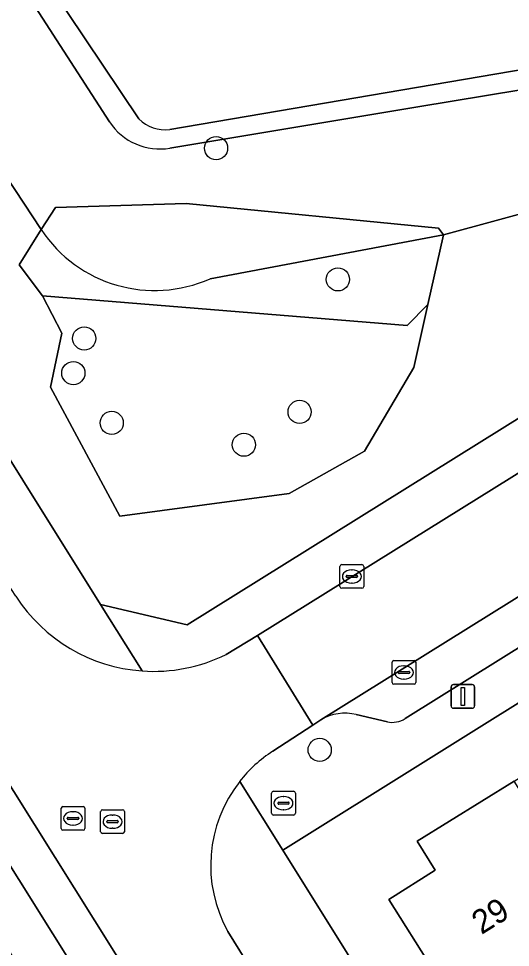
# Model space of a CAD drawing. Extents: x 159664 to 160323, y 385312 to 386115.
# Drawn here: x 159837.52 to 159858.24, y 385888.33 to 385927.51 of the extents above; entities that cross this region are included whole.
import ezdxf

# ---------------------------------------------------------------- set-up
doc = ezdxf.new("R2010")
doc.units = 0
for name, color, linetype in [('IMGEO_Boom', 7, 'Continuous'), ('IMGEO_Brandkraan', 7, 'Continuous'), ('IMGEO_Erf', 7, 'Continuous'), ('IMGEO_Groenvoorziening', 7, 'Continuous'), ('IMGEO_Kolk', 7, 'Continuous'), ('IMGEO_Lichtmast', 7, 'Continuous'), ('IMGEO_Meer_plas_ven_vijver', 7, 'Continuous'), ('IMGEO_Oever', 7, 'Continuous'), ('IMGEO_Pand', 7, 'Continuous'), ('IMGEO_Pand_nummerreeks', 7, 'Continuous'), ('IMGEO_Parkeervlak_open', 7, 'Continuous'), ('IMGEO_Rijbaan_lokaal_open', 7, 'Continuous'), ('IMGEO_Rioolput', 7, 'Continuous'), ('IMGEO_Voetpad_open', 7, 'Continuous')]:
    doc.layers.add(name, color=color, linetype=linetype)

msp = doc.modelspace()

# ---------------------------------------------------------------- linework, layer by layer
at = {"layer": 'IMGEO_Boom'}
for centre in [(159845.842, 385922.048), (159850.977, 385916.513), (159840.289, 385914.022), (159839.829, 385912.56), (159849.363, 385910.923), (159841.446, 385910.459), (159847.015, 385909.539), (159850.209, 385896.665)]:
    msp.add_circle(centre, 0.489, dxfattribs=at)
at = {"layer": 'IMGEO_Brandkraan'}
for p, q in [((159848.182, 385893.993), (159848.182, 385894.845)), ((159848.257, 385894.919), (159849.109, 385894.919)), ((159848.67, 385894.699), (159848.695, 385894.699)), ((159849.183, 385894.845), (159849.183, 385893.993)), ((159848.441, 385894.413), (159848.441, 385894.425)), ((159848.879, 385894.376), (159848.481, 385894.376)), ((159848.484, 385894.462), (159848.882, 385894.462)), ((159848.925, 385894.425), (159848.925, 385894.413)), ((159849.109, 385893.919), (159848.257, 385893.919)), ((159848.693, 385894.139), (159848.668, 385894.139))]:
    msp.add_line(p, q, dxfattribs=at)
for points in [[(159848.182, 385893.993), (159848.182, 385894.845)], [(159848.257, 385894.919), (159849.109, 385894.919)], [(159849.183, 385894.845), (159849.183, 385893.993)], [(159849.109, 385893.919), (159848.257, 385893.919)]]:
    msp.add_lwpolyline(points, dxfattribs=at)
for centre, radius, start, end in [((159848.259, 385894.843), 0.0765, 91.552, 178.448), ((159848.259, 385894.843), 0.0765, 91.552, 178.448), ((159849.107, 385894.843), 0.0765, 1.552, 88.448), ((159849.107, 385894.843), 0.0765, 1.552, 88.448), ((159848.481, 385894.422), 0.0403, 85.8775, 175.7526), ((159848.478, 385894.412), 0.0366, 178.938, 274.7102), ((159848.882, 385894.419), 0.043, 264.8664, 352.4533), ((159848.886, 385894.424), 0.0386, 1.7309, 96.639), ((159848.259, 385893.995), 0.0765, 181.552, 268.448), ((159848.259, 385893.995), 0.0765, 181.552, 268.448), ((159849.107, 385893.995), 0.0765, 271.552, 358.448), ((159849.107, 385893.995), 0.0765, 271.552, 358.448)]:
    msp.add_arc(centre, radius, start, end, dxfattribs=at)
for centre, major_axis, ratio, start_param, end_param in [((159848.669, 385894.419), (-0.387, 0.002), 0.722429, 4.712389, 7.853982), ((159848.694, 385894.419), (-0.39, 0.002), 0.717154, 1.570796, 4.712389)]:
    msp.add_ellipse(centre, major_axis=major_axis, ratio=ratio, start_param=start_param, end_param=end_param, dxfattribs=at)
at = {"layer": 'IMGEO_Erf'}
for points in [[(159910.117, 385903.4), (159897.762, 385923.148), (159848.649, 385892.435), (159862.284, 385870.598)], [(159858.647, 385881.576), (159853.117, 385890.352), (159855.08, 385891.589), (159854.319, 385892.812), (159858.396, 385895.35), (159861.083, 385897.023), (159862.264, 385896.739), (159864.086, 385897.883), (159866.508, 385899.404), (159866.729, 385900.359), (159868.222, 385901.297), (159869.161, 385901.055), (159869.407, 385901.202), (159869.672, 385901.361), (159869.899, 385902.316), (159871.378, 385903.268), (159872.318, 385903.03), (159874.694, 385904.513), (159877.06, 385905.991), (159877.276, 385906.941), (159878.764, 385907.881), (159879.712, 385907.648), (159880.006, 385907.827)]]:
    msp.add_lwpolyline(points, dxfattribs=at)
at = {"layer": 'IMGEO_Groenvoorziening'}
for points in [[(159816.297, 385948.623), (159815.724, 385950.966), (159815.963, 385953.118), (159815.58, 385954.17), (159814.146, 385955.461), (159811.994, 385956.513), (159811.037, 385957.804), (159811.468, 385959.287), (159812.472, 385960.291), (159812.807, 385961.678), (159812.663, 385963.686), (159812.339, 385964.66), (159805.18, 385960.168), (159840.98, 385902.792), (159844.627, 385901.937), (159897.826, 385935.149), (159897.089, 385936.287), (159896.974, 385936.212), (159896.463, 385937.027)], [(159825.341, 385947.546), (159823.184, 385946.559), (159821.022, 385946.602), (159820.348, 385946.616), (159820.789, 385945.508), (159838.479, 385918.611), (159839.072, 385919.548), (159844.581, 385919.713), (159855.219, 385918.667), (159855.427, 385918.399), (159863.832, 385920.689), (159866.297, 385921.953), (159870.044, 385923.874), (159871.106, 385924.495), (159870.716, 385924.674), (159869.124, 385925.404), (159865.913, 385927.638), (159862.758, 385925.65), (159861.486, 385925.086), (159860.136, 385924.752), (159854.341, 385923.788), (159843.899, 385922.051)], [(159841.353, 385923.154), (159833.178, 385935.808), (159832.783, 385936.389), (159832.404, 385936.945), (159825.341, 385947.546)], [(159893.074, 385936.712), (159888.397, 385934.574), (159883.316, 385931.913), (159878.038, 385928.61), (159876.477, 385927.633), (159871.106, 385924.495), (159870.044, 385923.874), (159866.297, 385921.953), (159863.832, 385920.689), (159855.427, 385918.399), (159854.769, 385915.45), (159854.175, 385912.792), (159852.092, 385909.266), (159848.925, 385907.476), (159841.782, 385906.522), (159838.868, 385911.97), (159839.343, 385914.245), (159838.525, 385915.822), (159837.543, 385917.132), (159838.479, 385918.611), (159820.789, 385945.508)], [(159845.593, 385916.542), (159855.427, 385918.399), (159855.219, 385918.667), (159844.581, 385919.713), (159839.072, 385919.548), (159838.479, 385918.611)], [(159838.479, 385918.611), (159837.543, 385917.132), (159838.525, 385915.822), (159853.893, 385914.567), (159854.769, 385915.45), (159855.427, 385918.399), (159845.593, 385916.542)]]:
    msp.add_lwpolyline(points, dxfattribs=at)
msp.add_lwpolyline([(159854.175, 385912.792), (159854.769, 385915.45), (159853.893, 385914.567), (159838.525, 385915.822), (159839.343, 385914.245), (159838.868, 385911.97), (159841.782, 385906.522), (159848.925, 385907.476), (159852.092, 385909.266)], close=True, dxfattribs=at)
for centre, radius, start, end in [((159843.474, 385924.559), 2.544, 213.5278, 279.6249), ((159843.255, 385921.769), 5.726, 213.4728, 294.0947), ((159843.255, 385921.769), 5.726, 213.4728, 294.0947)]:
    msp.add_arc(centre, radius, start, end, dxfattribs=at)
at = {"layer": 'IMGEO_Kolk'}
for p, q in [((159851.063, 385903.556), (159851.063, 385904.408)), ((159851.138, 385904.482), (159851.99, 385904.482)), ((159852.064, 385904.408), (159852.064, 385903.556)), ((159851.365, 385904.025), (159851.763, 385904.025)), ((159851.551, 385904.262), (159851.576, 385904.262)), ((159851.322, 385903.976), (159851.322, 385903.988)), ((159851.76, 385903.939), (159851.362, 385903.939)), ((159851.574, 385903.702), (159851.549, 385903.702)), ((159851.806, 385903.988), (159851.806, 385903.976)), ((159851.99, 385903.482), (159851.138, 385903.482)), ((159853.259, 385899.508), (159853.259, 385900.36)), ((159853.334, 385900.434), (159854.186, 385900.434)), ((159853.747, 385900.214), (159853.772, 385900.214)), ((159854.26, 385900.36), (159854.26, 385899.508)), ((159853.518, 385899.928), (159853.518, 385899.94)), ((159853.956, 385899.891), (159853.558, 385899.891)), ((159853.561, 385899.977), (159853.959, 385899.977)), ((159854.002, 385899.94), (159854.002, 385899.928)), ((159854.186, 385899.434), (159853.334, 385899.434)), ((159853.77, 385899.654), (159853.745, 385899.654))]:
    msp.add_line(p, q, dxfattribs=at)
for points in [[(159851.063, 385903.556), (159851.063, 385904.408)], [(159851.138, 385904.482), (159851.99, 385904.482)], [(159852.064, 385904.408), (159852.064, 385903.556)], [(159851.99, 385903.482), (159851.138, 385903.482)], [(159853.259, 385899.508), (159853.259, 385900.36)], [(159853.334, 385900.434), (159854.186, 385900.434)], [(159854.26, 385900.36), (159854.26, 385899.508)], [(159854.186, 385899.434), (159853.334, 385899.434)]]:
    msp.add_lwpolyline(points, dxfattribs=at)
for centre, radius, start, end in [((159851.14, 385904.406), 0.0765, 91.552, 178.448), ((159851.14, 385904.406), 0.0765, 91.552, 178.448), ((159851.988, 385904.406), 0.0765, 1.552, 88.448), ((159851.988, 385904.406), 0.0765, 1.552, 88.448), ((159851.362, 385903.985), 0.0403, 85.8775, 175.7526), ((159851.767, 385903.987), 0.0386, 1.7309, 96.639), ((159851.359, 385903.975), 0.0366, 178.938, 274.7102), ((159851.763, 385903.982), 0.043, 264.8664, 352.4533), ((159851.14, 385903.558), 0.0765, 181.552, 268.448), ((159851.14, 385903.558), 0.0765, 181.552, 268.448), ((159851.988, 385903.558), 0.0765, 271.552, 358.448), ((159851.988, 385903.558), 0.0765, 271.552, 358.448), ((159853.336, 385900.358), 0.0765, 91.552, 178.448), ((159853.336, 385900.358), 0.0765, 91.552, 178.448), ((159854.184, 385900.358), 0.0765, 1.552, 88.448), ((159854.184, 385900.358), 0.0765, 1.552, 88.448), ((159853.558, 385899.937), 0.0403, 85.8775, 175.7526), ((159853.555, 385899.927), 0.0366, 178.938, 274.7102), ((159853.959, 385899.934), 0.043, 264.8664, 352.4533), ((159853.963, 385899.939), 0.0386, 1.7309, 96.639), ((159853.336, 385899.51), 0.0765, 181.552, 268.448), ((159853.336, 385899.51), 0.0765, 181.552, 268.448), ((159854.184, 385899.51), 0.0765, 271.552, 358.448), ((159854.184, 385899.51), 0.0765, 271.552, 358.448)]:
    msp.add_arc(centre, radius, start, end, dxfattribs=at)
for centre, major_axis, ratio, start_param, end_param in [((159851.55, 385903.982), (-0.387, 0.002), 0.722429, 4.712389, 7.853982), ((159851.575, 385903.982), (-0.39, 0.002), 0.717154, 1.570796, 4.712389), ((159853.746, 385899.934), (-0.387, 0.002), 0.722429, 4.712389, 7.853982), ((159853.771, 385899.934), (-0.39, 0.002), 0.717154, 1.570796, 4.712389)]:
    msp.add_ellipse(centre, major_axis=major_axis, ratio=ratio, start_param=start_param, end_param=end_param, dxfattribs=at)
at = {"layer": 'IMGEO_Lichtmast'}
for p, q in [((159855.744, 385898.52), (159855.744, 385899.32)), ((159855.744, 385899.32), (159855.744, 385898.52)), ((159855.844, 385899.42), (159856.634, 385899.42)), ((159856.634, 385899.42), (159855.844, 385899.42)), ((159856.734, 385899.32), (159856.734, 385898.52)), ((159856.734, 385898.52), (159856.734, 385899.32)), ((159856.634, 385898.42), (159855.844, 385898.42)), ((159855.844, 385898.42), (159856.634, 385898.42))]:
    msp.add_line(p, q, dxfattribs=at)
msp.add_lwpolyline([(159856.164, 385899.295), (159856.314, 385899.295), (159856.314, 385898.545), (159856.164, 385898.545), (159856.164, 385899.295)], dxfattribs=at)
for centre, start, end in [((159855.844, 385899.32), 90, 180), ((159855.844, 385899.32), 90, 180), ((159856.634, 385899.32), 0, 90), ((159856.634, 385899.32), 360, 90), ((159855.844, 385898.52), 180, 270), ((159855.844, 385898.52), 180, 270), ((159856.634, 385898.52), 270, 0), ((159856.634, 385898.52), 270, 0)]:
    msp.add_arc(centre, 0.1, start, end, dxfattribs=at)
at = {"layer": 'IMGEO_Meer_plas_ven_vijver'}
for points in [[(159826.015, 385948.406), (159832.55, 385938.234), (159832.749, 385937.963), (159832.404, 385936.945), (159832.783, 385936.389), (159833.178, 385935.808), (159834.079, 385935.928), (159834.268, 385935.688), (159842.589, 385923.279)], [(159843.891, 385922.833), (159859.565, 385925.503)]]:
    msp.add_lwpolyline(points, dxfattribs=at)
msp.add_arc((159843.712, 385924.434), 1.611, 225.8106, 276.3716, dxfattribs=at)
at = {"layer": 'IMGEO_Oever'}
for points in [[(159842.589, 385923.279), (159834.268, 385935.688), (159834.079, 385935.928), (159833.178, 385935.808), (159841.353, 385923.154)], [(159843.899, 385922.051), (159854.341, 385923.788), (159860.136, 385924.752), (159861.486, 385925.086), (159862.758, 385925.65), (159865.913, 385927.638), (159871.116, 385930.915), (159878.047, 385935.282)], [(159859.565, 385925.503), (159843.891, 385922.833)]]:
    msp.add_lwpolyline(points, dxfattribs=at)
for centre, radius, start, end in [((159843.712, 385924.434), 1.611, 225.8106, 276.3716), ((159843.474, 385924.559), 2.544, 213.5278, 279.6249)]:
    msp.add_arc(centre, radius, start, end, dxfattribs=at)
at = {"layer": 'IMGEO_Pand'}
msp.add_lwpolyline([(159858.396, 385895.35), (159854.319, 385892.812), (159855.08, 385891.589), (159853.117, 385890.352), (159858.647, 385881.576), (159861.689, 385883.482), (159859.863, 385886.397), (159862.856, 385888.272)], close=True, dxfattribs=at)
at = {"layer": 'IMGEO_Parkeervlak_open'}
for points in [[(159799.613, 385951.857), (159841.754, 385884.442), (159843.279, 385885.394), (159833.101, 385901.651)], [(159892.845, 385924.491), (159850.261, 385897.937)], [(159853.804, 385897.989), (159891.173, 385921.316)], [(159851.747, 385898.155), (159853.059, 385897.846)]]:
    msp.add_lwpolyline(points, dxfattribs=at)
for centre, radius, start, end in [((159851.275, 385896.201), 2.01, 76.4117, 120.2801), ((159853.26, 385898.811), 0.986, 258.2347, 303.4964)]:
    msp.add_arc(centre, radius, start, end, dxfattribs=at)
at = {"layer": 'IMGEO_Rijbaan_lokaal_open'}
msp.add_lwpolyline([(159893.557, 385924.936), (159891.196, 385928.691), (159847.59, 385901.495), (159849.923, 385897.713), (159850.261, 385897.937), (159892.845, 385924.491)], close=True, dxfattribs=at)
for points in [[(159837.407, 385903.15), (159836.858, 385903.992), (159833.101, 385901.651), (159843.279, 385885.394), (159847.097, 385887.778), (159846.34, 385889.002)], [(159849.923, 385897.713), (159847.59, 385901.495), (159846.264, 385900.693)], [(159848.231, 385896.611), (159849.923, 385897.713)]]:
    msp.add_lwpolyline(points, dxfattribs=at)
for centre, radius, start, end in [((159843.211, 385906.875), 6.896, 212.6943, 265.9535), ((159843.208, 385906.875), 6.896, 265.9735, 296.3037), ((159851.335, 385891.815), 5.713, 122.9116, 141.9378), ((159851.356, 385891.795), 5.741, 141.9133, 209.115)]:
    msp.add_arc(centre, radius, start, end, dxfattribs=at)
at = {"layer": 'IMGEO_Rioolput'}
for p, q in [((159839.39, 385894.277), (159840.242, 385894.277)), ((159839.315, 385893.351), (159839.315, 385894.203)), ((159839.617, 385893.82), (159840.015, 385893.82)), ((159839.803, 385894.057), (159839.828, 385894.057)), ((159840.316, 385894.203), (159840.316, 385893.351)), ((159840.98, 385893.213), (159840.98, 385894.065)), ((159841.055, 385894.139), (159841.907, 385894.139)), ((159841.468, 385893.919), (159841.493, 385893.919)), ((159841.981, 385894.065), (159841.981, 385893.213)), ((159839.574, 385893.771), (159839.574, 385893.783)), ((159840.012, 385893.734), (159839.614, 385893.734)), ((159839.826, 385893.497), (159839.801, 385893.497)), ((159840.058, 385893.783), (159840.058, 385893.771)), ((159841.239, 385893.633), (159841.239, 385893.645)), ((159841.677, 385893.596), (159841.279, 385893.596)), ((159841.282, 385893.682), (159841.68, 385893.682)), ((159841.723, 385893.645), (159841.723, 385893.633)), ((159840.242, 385893.277), (159839.39, 385893.277)), ((159841.907, 385893.139), (159841.055, 385893.139)), ((159841.491, 385893.359), (159841.466, 385893.359))]:
    msp.add_line(p, q, dxfattribs=at)
for points in [[(159839.39, 385894.277), (159840.242, 385894.277)], [(159839.315, 385893.351), (159839.315, 385894.203)], [(159840.316, 385894.203), (159840.316, 385893.351)], [(159840.98, 385893.213), (159840.98, 385894.065)], [(159841.055, 385894.139), (159841.907, 385894.139)], [(159841.981, 385894.065), (159841.981, 385893.213)], [(159840.242, 385893.277), (159839.39, 385893.277)], [(159841.907, 385893.139), (159841.055, 385893.139)]]:
    msp.add_lwpolyline(points, dxfattribs=at)
for centre, radius, start, end in [((159839.392, 385894.201), 0.0765, 91.552, 178.448), ((159839.392, 385894.201), 0.0765, 91.552, 178.448), ((159840.24, 385894.201), 0.0765, 1.552, 88.448), ((159840.24, 385894.201), 0.0765, 1.552, 88.448), ((159839.614, 385893.78), 0.0403, 85.8775, 175.7526), ((159840.019, 385893.782), 0.0386, 1.7309, 96.639), ((159841.057, 385894.063), 0.0765, 91.552, 178.448), ((159841.057, 385894.063), 0.0765, 91.552, 178.448), ((159841.905, 385894.063), 0.0765, 1.552, 88.448), ((159841.905, 385894.063), 0.0765, 1.552, 88.448), ((159839.611, 385893.77), 0.0366, 178.938, 274.7102), ((159840.015, 385893.777), 0.043, 264.8664, 352.4533), ((159841.279, 385893.642), 0.0403, 85.8775, 175.7526), ((159841.276, 385893.632), 0.0366, 178.938, 274.7102), ((159841.68, 385893.639), 0.043, 264.8664, 352.4533), ((159841.684, 385893.644), 0.0386, 1.7309, 96.639), ((159839.392, 385893.353), 0.0765, 181.552, 268.448), ((159839.392, 385893.353), 0.0765, 181.552, 268.448), ((159840.24, 385893.353), 0.0765, 271.552, 358.448), ((159840.24, 385893.353), 0.0765, 271.552, 358.448), ((159841.057, 385893.215), 0.0765, 181.552, 268.448), ((159841.057, 385893.215), 0.0765, 181.552, 268.448), ((159841.905, 385893.215), 0.0765, 271.552, 358.448), ((159841.905, 385893.215), 0.0765, 271.552, 358.448)]:
    msp.add_arc(centre, radius, start, end, dxfattribs=at)
for centre, major_axis, ratio, start_param, end_param in [((159839.802, 385893.777), (-0.387, 0.002), 0.722429, 4.712389, 7.853982), ((159839.827, 385893.777), (-0.39, 0.002), 0.717154, 1.570796, 4.712389), ((159841.467, 385893.639), (-0.387, 0.002), 0.722429, 4.712389, 7.853982), ((159841.492, 385893.639), (-0.39, 0.002), 0.717154, 1.570796, 4.712389)]:
    msp.add_ellipse(centre, major_axis=major_axis, ratio=ratio, start_param=start_param, end_param=end_param, dxfattribs=at)
at = {"layer": 'IMGEO_Voetpad_open'}
for points in [[(159957.008, 385971.838), (159955.282, 385972.677), (159953.545, 385970.025), (159900.817, 385937.026), (159900.054, 385938.175), (159899.814, 385938.011), (159897.205, 385936.362), (159897.089, 385936.287), (159897.826, 385935.149), (159844.627, 385901.937), (159840.98, 385902.792), (159842.724, 385899.996)], [(159846.264, 385900.693), (159847.59, 385901.495), (159891.196, 385928.691), (159908.969, 385939.82), (159952.436, 385967.026)], [(159842.724, 385899.996), (159840.98, 385902.792), (159805.18, 385960.168)], [(159799.513, 385955.383), (159798.855, 385956.375), (159795.686, 385954.403), (159814.677, 385924.046), (159815.439, 385922.828), (159840.099, 385883.409), (159841.754, 385884.442), (159799.613, 385951.857)], [(159846.837, 385895.337), (159848.649, 385892.435), (159897.762, 385923.148)], [(159891.173, 385921.316), (159853.804, 385897.989)], [(159853.059, 385897.846), (159851.747, 385898.155)], [(159850.261, 385897.937), (159849.923, 385897.713), (159848.231, 385896.611)], [(159898.799, 385812.12), (159896.671, 385815.527), (159863.075, 385869.332), (159862.284, 385870.598), (159848.649, 385892.435), (159846.837, 385895.337)], [(159846.34, 385889.002), (159847.097, 385887.778), (159848.027, 385886.266)]]:
    msp.add_lwpolyline(points, dxfattribs=at)
for centre, radius, start, end in [((159843.211, 385906.875), 6.896, 212.6943, 265.9535), ((159843.208, 385906.875), 6.896, 265.9735, 296.3037), ((159851.275, 385896.201), 2.01, 76.4117, 120.2801), ((159853.26, 385898.811), 0.986, 258.2347, 303.4964), ((159851.335, 385891.815), 5.713, 122.9116, 141.9378), ((159851.356, 385891.795), 5.741, 141.9133, 209.115)]:
    msp.add_arc(centre, radius, start, end, dxfattribs=at)

# ---------------------------------------------------------------- texts
at = {"layer": 'IMGEO_Pand_nummerreeks'}
msp.add_text('29', height=1, rotation=32.0066, dxfattribs=at).set_placement((159857.024, 385888.854))

doc.saveas('drawing.dxf')
